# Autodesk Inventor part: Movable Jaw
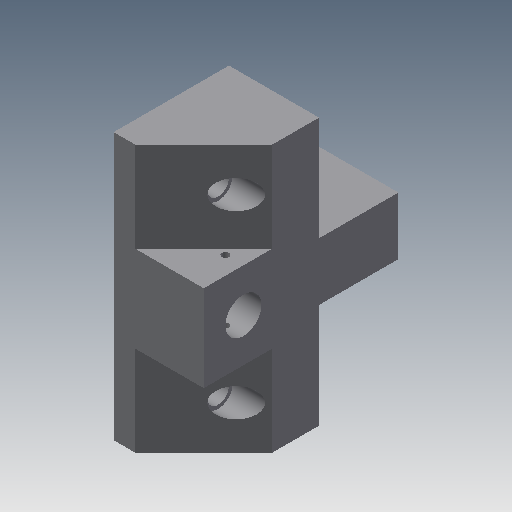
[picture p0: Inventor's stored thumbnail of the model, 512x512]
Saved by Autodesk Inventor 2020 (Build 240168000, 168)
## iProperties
Created: 2002-02
Part Number: Movable Jaw
Document SubType Name: Modeling
Designer: ***
Density: 1 g/cm^3
Material: Generic
Appearance: Default
Control State: 0
Master: False
Checked Out: False
Shininess: 77.0
Length Units: 11269
Angle Units: 11279
Time Units: 11290
Mass Units: 11283
Length Display Precision: 3
Angle Display Precision: 2
Density: 0.0
Volumn: 0.0
Area: 0.0
PropertySet Name: Model Information
Author: ***
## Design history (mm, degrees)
sketch "Sketch2"
  geometry: L1 (2.39, 41.509)-(2.39, 9.509); L2 (2.39, 9.509)-(-22.61, 9.509); L3 (-22.61, 9.509)-(-22.61, 22.509); L4 (-22.61, 22.509)-(-3.61, 41.509); L5 (-3.61, 41.509)-(2.39, 41.509)
  constraints: 10 end point, 2 parallel, 1 perpendicular, 1 vertical
  dimensions: "d0" = 25 distance of L1.end L2.end; "d2" = 13 distance of L2.end L3.end; "d3" = 32 distance between parallel lines of L5 L2; "d4" = 6 distance of L4.end L1.start
extrude "Extrusion1" new body sketch "Sketch2" stored distance "d5" = 74; taper "d6" = 0 deg
sketch "Sketch3"
  geometry: L1 (-19, 25)-(11, 25); L2 (11, 25)-(11, 49); L3 (11, 49)-(-19, 49); L4 (-19, 49)-(-19, 25); L5 (0, 0)-(13, 0) reference; L6 (-19, 74)-(-19, 0) reference; L7 (11.924, 29)-(35, 29); L8 (35, 29)-(35, 45); L9 (35, 45)-(11.924, 45); L10 (11.924, 45)-(11.924, 29); L11 (13, 74)-(13, 0) reference
  constraints: 16 end point, 4 parallel, 2 horizontal, 2 perpendicular, 1 collinear
  dimensions: "d7" = 24 distance of L3.end L1.start; "d8" = 30 distance of L1.start L1.end; "d9" = 25 distance between parallel lines of L5 L1; "d10" = 16 distance of L7.end L8.end; "d11" = 4 distance between parallel lines of L3 L9; "d12" = 22 distance between parallel lines of L11 L8
extrude "Extrusion2" join sketch "Sketch3" distance "d13" = 25; taper "d14" = 0 deg
sketch "Sketch4"
  geometry: L1 (-19, -25)-(-19, -49) reference; L2 (-19, -49)-(0, -49) reference; 1 further point
  dimensions: "d15" = 11 distance from line of L1 point (-8, -37); "d16" = 12 distance from line of L2 point (-8, -37)
hole "Hole1" sketch "Sketch4" at (-8, -37) diameter "d17" = 10; stored, may be unused: countersink angle "d21" = 82 deg, drill point angle "d23" = 0 deg; dims "d18" = 6, "d19" = 4, "d20" = 2, "d22" = 13
sketch "Sketch5"
  geometry: L1 (-19, -49)-(-19, -74) reference; L2 (0, -74)-(13, -74) reference; 1 further point
  dimensions: "d24" = 14 distance from line of L1 point (-5, -62); "d25" = 12 distance from line of L2 point (-5, -62)
hole "Hole2" sketch "Sketch5" at (-5, -62) diameter "d26" = 6; stored, may be unused: countersink angle "d30" = 82 deg, drill point angle "d32" = 0 deg; dims "d27" = 6, "d28" = 8, "d29" = 10, "d31" = 13
mirror "Mirror1"
sketch "Sketch6"
  geometry: L1 (0, 19)-(0, 0) reference; 1 further point
  dimensions: "d33" = 5 distance from line of L1 point (-5, 8); "d34" = 11 vertical distance of L1.start point (-5, 8)
hole "Hole3" sketch "Sketch6" at (-5, 8) diameter "d35" = 2; stored, may be unused: countersink angle "d39" = 82 deg, drill point angle "d41" = 0 deg; dims "d36" = 6, "d37" = 8, "d38" = 10, "d40" = 13
body "Solid1"
